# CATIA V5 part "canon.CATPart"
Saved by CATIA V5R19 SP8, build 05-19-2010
Part number: canon
Bounding box of the stored display mesh (mm): x -195 to 195, y -450 to 5400, z -150 to 344.855
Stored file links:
  G:\EU_thinkMotion\CFAO_2010\MMS_groupe2\MMS_groupe2\OK\mmartini\mmartiniCFAO\canon.CATPart
  C:\Users\Mathieu Martini\Desktop\CFAO\Animation\CFAO.CATProduct
  G:\EU_thinkMotion\CFAO_2010\MMS_groupe2\MMS_groupe2\OK\mmartini\mmartiniCFAO\Squelette.CATPart
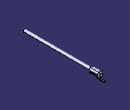
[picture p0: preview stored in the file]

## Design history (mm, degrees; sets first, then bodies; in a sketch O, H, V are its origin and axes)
External parameters (linked from other documents)
  External.diametre_canon = 150 mm
AxisSystem1: origin (0, 0, 0), X (1, 0, 0), Y (0, 1, 0), Z (0, 0, 1)
Set1
  Sketch1 on Plane1, origin (0, 0, 0), H (-1, 0, 0), V (0, 0, 1)
    circle A1 centre (0, 150) radius 75
    point P1 (0, 150)
    reference projected point E1 (0, 150) from Point1
    circle A2 centre (0, 150) radius 105
    point P2 (0, 150)
    radius A2 = 105 {= External.diametre_canon /2+External.diametre_canon /5}
    radius A1 = 75 {= External.diametre_canon /2}
    coincidence: P1 E1, P2 P1
Set2
  Plane1: linked copy from another document
  Point1 "pt_canonvertical": linked copy from another document
  Plane2 "fin_canon": linked copy from another document
  Plane3 "Plan_fin_canon": linked copy from another document
  Plane4: linked copy from another document
  Line1 "axe_canon": linked copy from another document
Body1 (main body)
  Pad1: profile Sketch1, direction (0, 1, 0), up to Plane2, opposite side up to Plane3
  Sketch2 on Plane4, origin (0, 0, 0), H (0, 1, 0), V (0, 0, 1)
    point P1 (5100, 255)
    reference projected line E1 through (0, 150) direction (1, 0) from Line1
    reference intersected line E2 through (5100, 0) direction (0, 1) from Plane3
    line L1 (5100, 255) -> (5010, 345)
    point P2 (5010, 345)
    line L2 (5010, 345) -> (4410, 345)
    line L3 (4410, 345) -> (4410, 285)
    line L4 (4410, 285) -> (4350, 285)
    line L5 (4350, 285) -> (4350, 255)
    line L6 (4350, 255) -> (5100, 255)
    distance P1 E1 = 105 {= External.diametre_canon /2+External.diametre_canon /5}
    distance P1 E2 = 0
    distance P2 P1 H = 90 {= External.diametre_canon /5*3}
    distance L2 L6 = 90 {= External.diametre_canon /5*3}
    length L2 = 600 {= External.diametre_canon *4}
    length L4 = 60 {= External.diametre_canon /10*4}
    length L5 = 30 {= External.diametre_canon /5}
    horizontal: L2 H, L4 H, L6 H
    vertical: L3 V, L5 V
  Shaft1: profile Sketch2, axis Line1, angle 360
  Sketch3 on Plane4, origin (0, 0, 0), H (0, 1, 0), V (0, 0, 1)
    point P1 (5100, -150)
    reference intersected line E1 through (5100, 0) direction (0, 1) from Plane3
    line L1 (5100, -150) -> (4950, -150)
    line L2 (4950, -150) -> (4500, 45)
    point P3 (4500, 45)
    line L3 (5100, -150) -> (5400, -150)
    line L4 (5400, -150) -> (5400, -105)
    line L5 (5400, -105) -> (5025, -105)
    reference projected line E2 through (0, 150) direction (1, 0) from Line1
    reference projected line E3 through (0, 150) direction (1, 0) from Line1
    line L6 (4500, 45) -> (4650, 45)
    point P7 (4650, 45)
    line L7 (5025, -105) -> (4650, 45)
    point P8 (4650, 45)
    length L4 = 45 {= External.diametre_canon /10*3}
    length L3 = 300 {= External.diametre_canon *2}
    distance L3 E2 = 300 {= External.diametre_canon *2}
    distance P3 E3 = 105 {= External.diametre_canon /5+External.diametre_canon /2}
    length L2 H = 450 {= External.diametre_canon *3}
    length L1 = 150 {= External.diametre_canon *1}
    length L5 = 375 {= External.diametre_canon *2.5}
    length L6 = 150 {= External.diametre_canon}
    coincidence: P1 E1, P7 L7, P7 P8
    horizontal: L1 H, L3 H, L5 H, L6 H
    vertical: L4 V
  Pad2: profile Sketch3, direction (1, 0, 0), length 45 {= External.diametre_canon /10*3}, mirrored extent
  Sketch4 on Plane4, origin (0, 0, 0), H (0, 1, 0), V (0, 0, 1)
    line L1 (4920, 218.1818) -> (4950, 218.1818)
    line L2 (4950, 218.1818) -> (4950, 81.8182)
    line L3 (4950, 81.8182) -> (4920, 81.8182)
    line L4 (4920, 81.8182) -> (4920, 218.1818)
    reference projected line E1 through (0, 150) direction (1, 0) from Line1
    reference intersected line E2 through (5100, 0) direction (0, 1) from Plane3
    length L1 = 30 {= External.diametre_canon /10*2}
    length L2 = 136.3636 {= External.diametre_canon/1.1}
    distance L1 E1 = 68.1818 {= External.diametre_canon /2.2}
    distance L2 E2 = 150 {= External.diametre_canon}
    horizontal: L1 H, L3 H
    vertical: L2 V, L4 V
  Pocket1: profile Sketch4, direction (-1, 0, 0), through (limit type 3), opposite side through (limit type 3)
  RectPattern1: of Pocket1, direction 1 instances 6, spacing 85.7143 {= External.diametre_canon /1.75}, along Line1 reversed
  Fillet1: radius 15 {= External.diametre_canon /10}, on edge [face of Pad2 from Sketch3.L7 | face of Shaft1 from Sketch2.L2]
